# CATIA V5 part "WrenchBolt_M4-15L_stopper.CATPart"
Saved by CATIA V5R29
Part number: WrenchBolt_M4-15L_Stopper
Bounding box of the stored display mesh (mm): x -3.61 to 3.61, y -3.61 to 3.61, z -15 to 4
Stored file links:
  C:\Users\Administrator\Desktop\10-14 작업\stopper\WrenchBolt_M4-15L_stopper.CATPart
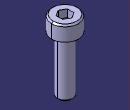
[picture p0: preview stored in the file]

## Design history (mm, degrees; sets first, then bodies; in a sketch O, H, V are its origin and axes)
Body1 (main body)
  Sketch1 on xy-plane, origin (0, 0, 0), H (1, 0, 0), V (0, 1, 0)
    circle A1 centre (0, 0) radius 3.61
    radius A1 = 3.61
  Pad1: profile Sketch1, direction (0, 0, 1), length 4
  Sketch2 on start face of Pad1, origin (0, 0, 0), H (1, 0, 0), V (0, -1, 0)
    circle A1 centre (0, 0) radius 2
    radius A1 = 2
  Pad2: profile Sketch2, direction (0, 0, -1), length 15
  Sketch3 on end face of Pad1, origin (0, 0, 4), H (1, 0, 0), V (0, 1, 0)
    point P1 (1.54, 0)
    construction circle A1 centre (0, 0) radius 1.7782
    construction circle A2 centre (0, 0) radius 1.54
    point P2 (1.54, -0.8891)
    point P3 (1.54, 0.8891)
    point P4 (0, 1.7782)
    point P5 (-1.54, 0.8891)
    point P6 (-1.54, -0.8891)
    point P7 (0, -1.7782)
    line L1 (1.54, -0.8891) -> (1.54, 0.8891)
    line L2 (1.54, 0.8891) -> (0, 1.7782)
    line L3 (0, 1.7782) -> (-1.54, 0.8891)
    line L4 (-1.54, 0.8891) -> (-1.54, -0.8891)
    line L5 (-1.54, -0.8891) -> (0, -1.7782)
    line L6 (0, -1.7782) -> (1.54, -0.8891)
    construction line L7 (0, 0) -> (1.54, 0)
    radius A2 = 1.54
    coincidence: A1 P2, A1 P3, A1 P4, A1 P5, A1 P6, A1 P7
    tangency: A2 L1, A2 L2, A2 L3, A2 L4, A2 L5, A2 L6
    midpoint: P1 L1
    horizontal: L7 H
  Pocket1: profile Sketch3, direction (0, 0, -1), length 2
  Thread1: "M4", diameter 4, depth 15, pitch 0.7, on face of Pad2 from Sketch2.A1, from end face of Pad2
  Chamfer1: length 0.4, angle 45, on end face of Pad2; edge [face of Pad1 from Sketch1.A1 | end face of Pad1]
  Fillet1: radius 0.2, on edge [start face of Pad1 | face of Pad2 from Sketch2.A1]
